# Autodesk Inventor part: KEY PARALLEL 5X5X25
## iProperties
Created: 2007-06
Part Number: KEY PARALLEL 5X5X25
Document SubType Name: Modeling
Designer: Andy Moles
Material: Steel
Density: 7.85 g/cm^3
Author: Andy Moles
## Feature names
1. Extrusion4
2. Fillet1
